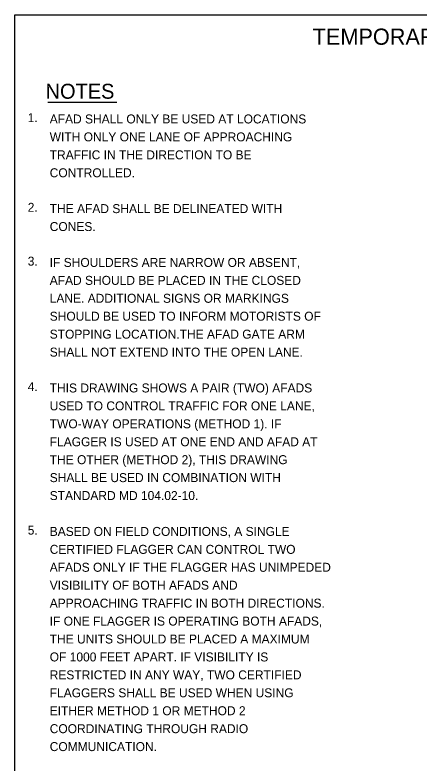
# Model space of a CAD drawing. Extents: x 21.7 to 29.1, y 5.9 to 16.2.
# Drawn here: x 21.72 to 24.42, y 11.2 to 16.21 of the extents above; entities that cross this region are included whole.
import ezdxf

# ---------------------------------------------------------------- set-up
doc = ezdxf.new("R2010")
doc.units = 0
for name, color, linetype in [('BORD-LINE', 7, 'Continuous'), ('DETL-LINE', 7, 'Continuous'), ('DETL-NOTE', 7, 'Continuous'), ('DETL-TITL', 7, 'Continuous')]:
    doc.layers.add(name, color=color, linetype=linetype)

msp = doc.modelspace()

# ---------------------------------------------------------------- linework, layer by layer
at = {"layer": 'BORD-LINE'}
msp.add_lwpolyline([(21.7194, 16.2106), (29.0936, 16.2106), (29.0936, 5.8575), (21.7194, 5.8575)], close=True, dxfattribs=at)
at = {"layer": 'DETL-LINE'}
msp.add_line((21.9394, 15.6266), (22.4013, 15.6266), dxfattribs=at)

# ---------------------------------------------------------------- texts
at = {"layer": 'DETL-NOTE'}
for s, height, p in [('NOTES', 0.1, (21.9243, 15.6499)), ('1.', 0.06, (21.8048, 15.4932)), ('AFAD SHALL ONLY BE USED AT LOCATIONS ', 0.06, (21.952, 15.4846)), ('WITH ONLY ONE LANE OF APPROACHING ', 0.06, (21.952, 15.3646)), ('TRAFFIC IN THE DIRECTION TO BE ', 0.06, (21.952, 15.2446)), ('CONTROLLED.', 0.06, (21.952, 15.1246)), ('2.', 0.06, (21.8048, 14.8932)), ('THE AFAD SHALL BE DELINEATED WITH ', 0.06, (21.952, 14.8846)), ('CONES.', 0.06, (21.952, 14.7646)), ('3.', 0.06, (21.8048, 14.5332)), ('IF SHOULDERS ARE NARROW OR ABSENT, ', 0.06, (21.952, 14.5246)), ('AFAD SHOULD BE PLACED IN THE CLOSED ', 0.06, (21.952, 14.4046)), ('LANE. ADDITIONAL SIGNS OR MARKINGS ', 0.06, (21.952, 14.2846)), ('SHOULD BE USED TO INFORM MOTORISTS OF ', 0.06, (21.952, 14.1646)), ('STOPPING LOCATION.THE AFAD GATE ARM ', 0.06, (21.952, 14.0446)), ('SHALL NOT EXTEND INTO THE OPEN LANE.', 0.06, (21.952, 13.9246)), ('4.', 0.06, (21.8048, 13.6932)), ('THIS DRAWING SHOWS A PAIR (TWO) AFADS ', 0.06, (21.952, 13.6846)), ('USED TO CONTROL TRAFFIC FOR ONE LANE, ', 0.06, (21.952, 13.5646)), ('TWO-WAY OPERATIONS (METHOD 1). IF ', 0.06, (21.952, 13.4446)), ('FLAGGER IS USED AT ONE END AND AFAD AT ', 0.06, (21.952, 13.3246)), ('THE OTHER (METHOD 2), THIS DRAWING ', 0.06, (21.952, 13.2046)), ('SHALL BE USED IN COMBINATION WITH ', 0.06, (21.952, 13.0846)), ('STANDARD MD 104.02-10.', 0.06, (21.952, 12.9646)), ('5.', 0.06, (21.8048, 12.7332)), ('BASED ON FIELD CONDITIONS, A SINGLE ', 0.06, (21.952, 12.7246)), ('CERTIFIED FLAGGER CAN CONTROL TWO ', 0.06, (21.952, 12.6046)), ('AFADS ONLY IF THE FLAGGER HAS UNIMPEDED ', 0.06, (21.952, 12.4846)), ('VISIBILITY OF BOTH AFADS AND ', 0.06, (21.952, 12.3646)), ('APPROACHING TRAFFIC IN BOTH DIRECTIONS. ', 0.06, (21.952, 12.2446)), ('IF ONE FLAGGER IS OPERATING BOTH AFADS, ', 0.06, (21.952, 12.1246)), ('THE UNITS SHOULD BE PLACED A MAXIMUM ', 0.06, (21.952, 12.0046)), ('OF 1000 FEET APART. IF VISIBILITY IS ', 0.06, (21.952, 11.8846)), ('RESTRICTED IN ANY WAY, TWO CERTIFIED ', 0.06, (21.952, 11.7646)), ('FLAGGERS SHALL BE USED WHEN USING ', 0.06, (21.952, 11.6446)), ('EITHER METHOD 1 OR METHOD 2 ', 0.06, (21.952, 11.5246)), ('COORDINATING THROUGH RADIO ', 0.06, (21.952, 11.4046)), ('COMMUNICATION.', 0.06, (21.952, 11.2846))]:
    msp.add_text(s, height=height, dxfattribs=at).set_placement(p)
at = {"layer": 'DETL-TITL'}
msp.add_text('TEMPORARY TRAFFIC CONTROL TYPICAL APPLICATION', height=0.10852, dxfattribs=at).set_placement((23.7115, 16.011))

doc.saveas('drawing.dxf')
